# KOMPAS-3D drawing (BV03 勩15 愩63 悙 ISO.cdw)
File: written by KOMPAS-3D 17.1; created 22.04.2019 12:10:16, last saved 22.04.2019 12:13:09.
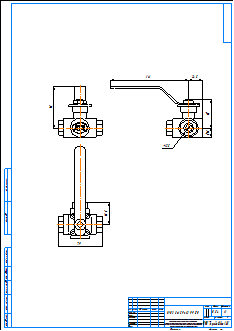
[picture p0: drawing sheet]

Sheet 1: A2, portrait

Title block, sheet 1: name: BV03 Ду15 Ру63 РР ISO; material: Внимание! Данный продукт является объектом авторского права ООО «Торговый Дом АДЛ». / Запрещается изменение, копирование, распространение / (в том числе путем копирования на другие сайты и ресурсы в Интернете) / или любое иное использование информации и объектов без предварительного / согласия правообладателя (ООО «Торговый Дом АДЛ»).; mass: 0,84; sheets: 1; organisation: ООО "Торговый дом АДЛ"; sheet format: A2

Views: Спереди 1, Проекционный вид 2, Проекционный вид 3
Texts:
  user
Dimensions and other numbers on the sheet: 75; 79; 39,5; 141; 24,5; 51; 17,5; 12,5; 1:1; 1; 0,84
